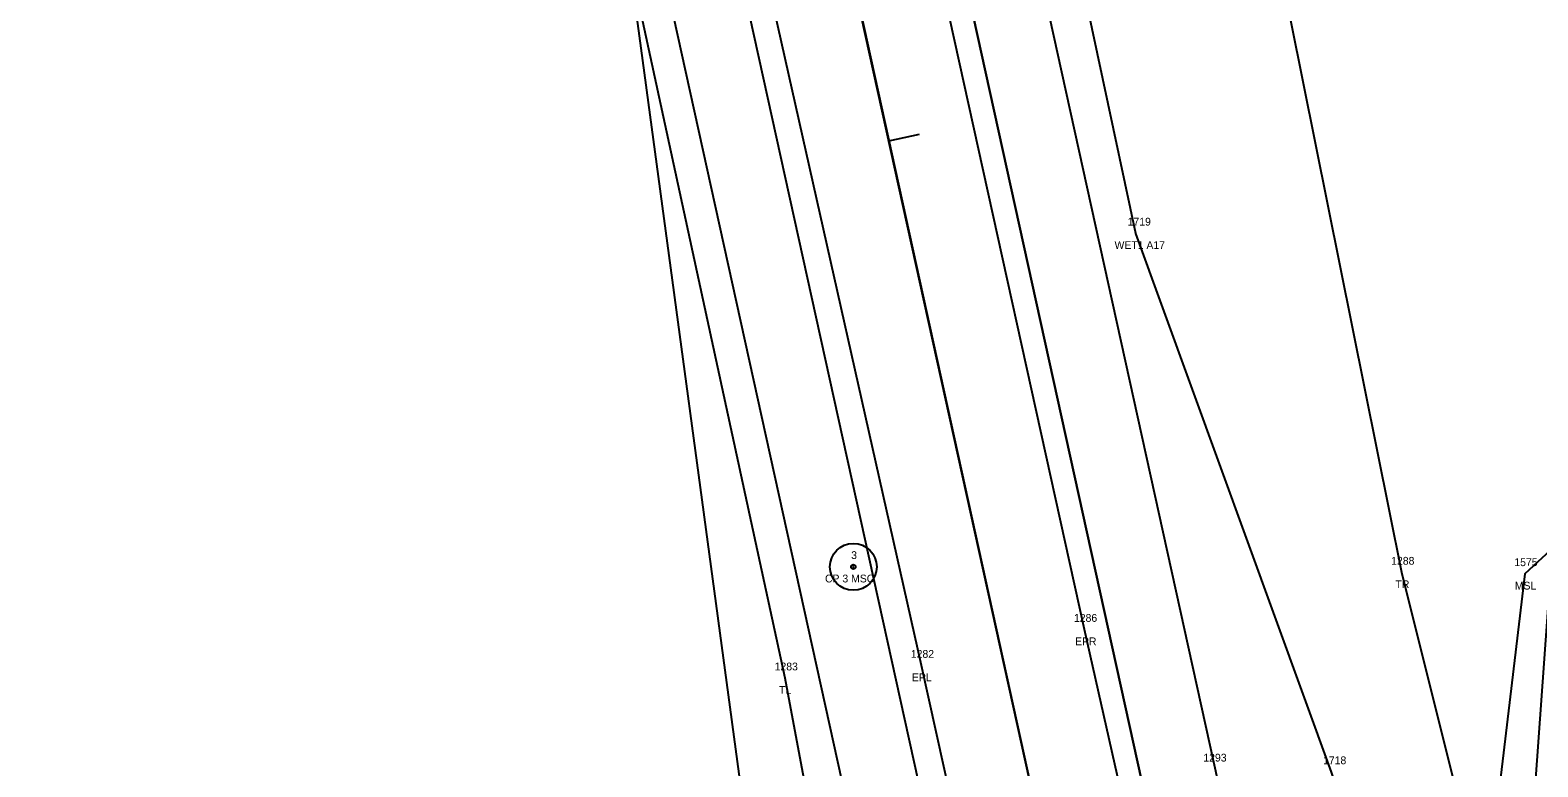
# Model space of a CAD drawing. Extents: x 2521558 to 2524785, y 882711 to 887632.
# Drawn here: x 2523636.1 to 2523829.3, y 885237.2 to 885331.6 of the extents above; entities that cross this region are included whole.
import ezdxf

# ---------------------------------------------------------------- set-up
doc = ezdxf.new("R2010")
doc.units = 0
for name, color, linetype in [('RD_EV_JurisArea', 7, 'Continuous'), ('RD_EX_GuardRail_txCode', 7, 'Continuous'), ('RD_EX_H2O', 7, 'Continuous'), ('RD_EX_H2O_WetLd_txCode', 7, 'Continuous'), ('RD_EX_Misc', 7, 'Continuous'), ('RD_EX_Misc_txCode', 7, 'Continuous'), ('RD_EX_Road', 7, 'Continuous'), ('RD_EX_Road_txCode', 7, 'Continuous'), ('RD_EX_VEG', 7, 'Continuous'), ('RD_EX_VEG_txCode', 7, 'Continuous'), ('RD_HC_Cl', 7, 'Continuous'), ('RD_HC_Data', 7, 'Continuous'), ('RD_HC_Data_Tic', 7, 'Continuous'), ('RD_HC_txCode', 7, 'Continuous'), ('RD_PD_Final_TrvlWay', 7, 'Continuous'), ('RD_PD_GR', 7, 'Continuous'), ('RD_PD_SuperShp1', 7, 'Continuous'), ('RD_SMD_Locator', 7, 'Continuous')]:
    doc.layers.add(name, color=color, linetype=linetype)

msp = doc.modelspace()

# ---------------------------------------------------------------- linework, layer by layer
at = {"layer": 'RD_EV_JurisArea'}
for points in [[(2523761.17, 885134.03), (2523740.58, 885149.03), (2523730.55, 885209.77), (2523710.6, 885357.47), (2523698.09, 885411.19), (2523674.93, 885498.62), (2523657.6, 885564.24), (2523640.82, 885610.87), (2523583.66, 885726.91), (2523539.21, 885693.17), (2523494.42, 885646.98)], [(2523761.17, 885134.03), (2523808.21, 885149.21), (2523821.91, 885178.64), (2523802.85, 885236.55), (2523777.81, 885305.56), (2523748.2, 885444.32), (2523730.68, 885516.88), (2523708.64, 885617.3), (2523698.71, 885662.02), (2523727.83, 885665.82), (2523757.3, 885671.75)]]:
    msp.add_lwpolyline(points, dxfattribs=at)
at = {"layer": 'RD_EX_H2O'}
msp.add_lwpolyline([(2524064.86, 885165.15), (2524036.37, 885213.78), (2524057.22, 885252.72), (2524031.95, 885291.63), (2523983.25, 885326.3), (2523940.61, 885311.83), (2523904.84, 885305.01), (2523874.98, 885272.1), (2523850.32, 885280.24), (2523830.66, 885258.8), (2523826.93, 885206.61)], dxfattribs=at)
at = {"layer": 'RD_EX_Misc'}
msp.add_lwpolyline([(2524066.31, 885165.35), (2524037.3, 885214.15), (2524057.95, 885253.07), (2524039.52, 885283.17), (2524032.92, 885292.57), (2523983.53, 885327.98), (2523940.24, 885313.27), (2523904.13, 885306.25), (2523874.86, 885272.67), (2523849.96, 885282.51), (2523827.65, 885261.93), (2523821.38, 885209.28)], dxfattribs=at)
at = {"layer": 'RD_EX_Road'}
for p, q in [((2523771.24, 885254.79), (2523751.35, 885344.92)), ((2523750.32, 885250.18), (2523730.02, 885340.63)), ((2523792.78, 885159.31), (2523771.24, 885254.79)), ((2523771.58, 885154.56), (2523750.32, 885250.18))]:
    msp.add_line(p, q, dxfattribs=at)
at = {"layer": 'RD_EX_VEG'}
for points in [[(2523825.62, 885207.01), (2523811.87, 885262.11), (2523733.02, 885654.22), (2523687.11, 885876.24)], [(2523749.81, 885158.06), (2523732.86, 885248.57), (2523691.62, 885438.95), (2523639.52, 885601.04)]]:
    msp.add_lwpolyline(points, dxfattribs=at)
at = {"layer": 'RD_HC_Cl'}
msp.add_line((2523641.17, 885794.2), (2524197.76, 883266.56), dxfattribs=at)
at = {"layer": 'RD_HC_Data'}
for radius in [3, 0.282]:
    msp.add_circle((2523741.6, 885262.84), radius, dxfattribs=at)
at = {"layer": 'RD_HC_Data_Tic'}
msp.add_line((2523746.15, 885317.42), (2523750.06, 885318.28), dxfattribs=at)
at = {"layer": 'RD_PD_Final_TrvlWay'}
for p, q in [((2523724.34, 885481.57), (2524039.39, 884050.85)), ((2523697, 885475.55), (2524012.05, 884044.83))]:
    msp.add_line(p, q, dxfattribs=at)
at = {"layer": 'RD_PD_GR'}
for p, q in [((2523722.6, 885533.67), (2523791.95, 885218.71)), ((2523746.05, 885208.61), (2523684.39, 885488.64))]:
    msp.add_line(p, q, dxfattribs=at)
at = {"layer": 'RD_PD_SuperShp1'}
for p, q in [((2524039.39, 884050.85), (2523724.34, 885481.57)), ((2524025.72, 884047.84), (2523710.67, 885478.56)), ((2523710.67, 885478.56), (2524025.72, 884047.84)), ((2523697, 885475.55), (2524012.05, 884044.83))]:
    msp.add_line(p, q, dxfattribs=at)
at = {"layer": 'RD_SMD_Locator'}
for centre in [(2523777.81, 885305.56), (2523741.6, 885262.84), (2523811.87, 885262.11), (2523827.65, 885261.93), (2523771.24, 885254.79), (2523750.32, 885250.18), (2523732.86, 885248.57)]:
    msp.add_circle(centre, 0.001, dxfattribs=at)

# ---------------------------------------------------------------- texts
at = {"layer": 'RD_EX_GuardRail_txCode'}
msp.add_text('1293', height=1, dxfattribs=at).set_placement((2523786.45, 885237.89))
at = {"layer": 'RD_EX_H2O_WetLd_txCode'}
for s, p in [('1719', (2523776.75, 885306.56)), ('WET1 A17', (2523775.07, 885303.56)), ('1718', (2523801.79, 885237.55))]:
    msp.add_text(s, height=1, dxfattribs=at).set_placement(p)
at = {"layer": 'RD_EX_Misc_txCode'}
for s, p in [('1575', (2523826.3, 885262.93)), ('MSL', (2523826.36, 885259.93))]:
    msp.add_text(s, height=1, dxfattribs=at).set_placement(p)
at = {"layer": 'RD_EX_Road_txCode'}
for s, p in [('1286', (2523769.87, 885255.79)), ('EPR', (2523770.01, 885252.79)), ('1282', (2523748.97, 885251.18)), ('EPL', (2523749.11, 885248.18))]:
    msp.add_text(s, height=1, dxfattribs=at).set_placement(p)
at = {"layer": 'RD_EX_VEG_txCode'}
for s, p in [('1288', (2523810.52, 885263.11)), ('TR', (2523811.07, 885260.11)), ('1283', (2523731.52, 885249.57)), ('TL', (2523732.09, 885246.57))]:
    msp.add_text(s, height=1, dxfattribs=at).set_placement(p)
at = {"layer": 'RD_HC_txCode'}
for s, p in [('3', (2523741.32, 885263.84)), ('CP 3 MSC', (2523737.97, 885260.84))]:
    msp.add_text(s, height=1, dxfattribs=at).set_placement(p)

doc.saveas('drawing.dxf')
